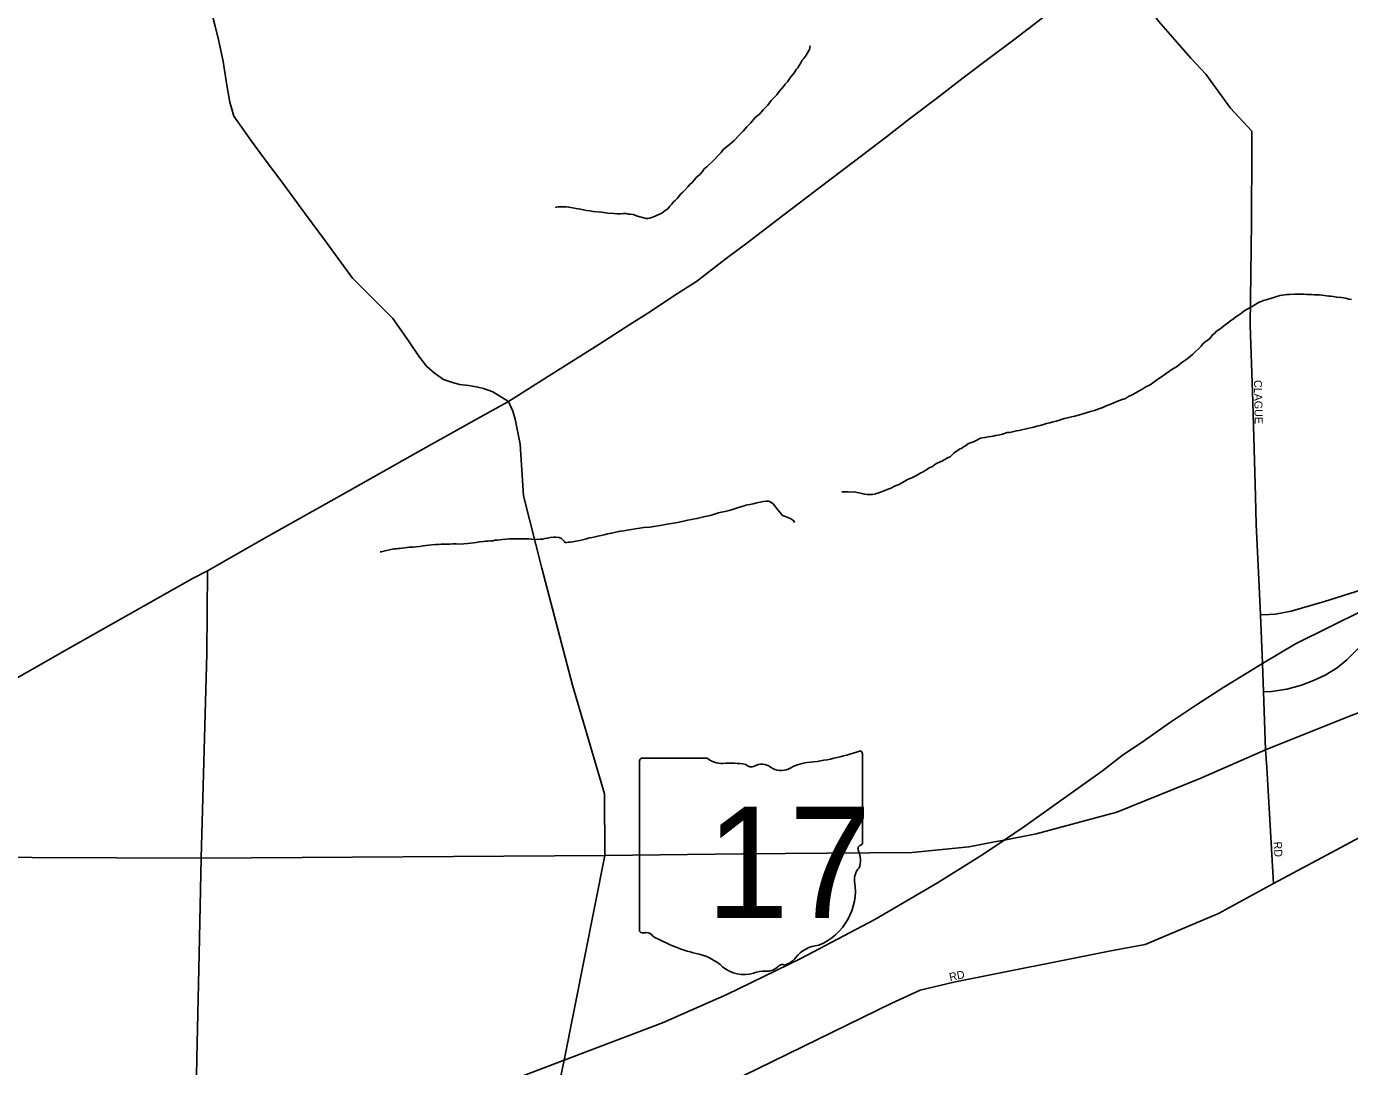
# Model space of a CAD drawing. Extents: x 2010165 to 2382125, y 1060529 to 1407316.
# Drawn here: x 2131582 to 2139850, y 1244739 to 1251239 of the extents above; entities that cross this region are included whole.
import ezdxf

# ---------------------------------------------------------------- set-up
doc = ezdxf.new("R2010")
doc.units = 0
for name, color, linetype in [('GM_X_City_Street', 7, 'Continuous'), ('GM_X_City_Street_Text', 7, 'Continuous'), ('GM_X_Interchange_Ramps', 7, 'Continuous'), ('GM_X_Interstate_Route', 7, 'Continuous'), ('GM_X_Minor_River', 7, 'Continuous'), ('GM_X_State_Location', 7, 'Continuous'), ('GM_X_State_Route', 7, 'Continuous'), ('GM_X_State_Shield', 7, 'Continuous')]:
    doc.layers.add(name, color=color, linetype=linetype)

msp = doc.modelspace()

# ---------------------------------------------------------------- linework, layer by layer
at = {"layer": 'GM_X_City_Street'}
for points in [[(2139262.6, 1248302.6), (2139246.4, 1248893.7), (2139229.9, 1249372.7), (2139237.4, 1250014), (2139239, 1250479), (2139238.9, 1250585.2), (2139106.7, 1250729.4), (2138951.7, 1250940.5), (2138858.6, 1251041.4), (2138757.8, 1251154.9), (2138656.8, 1251271.6), (2138619, 1251323.6), (2138585.9, 1251381.9), (2138552.8, 1251463.9), (2138515, 1251563.2), (2138464.5, 1251694.1)], [(2134760.7, 1243924.6), (2134781.7, 1244020.8), (2134942.2, 1244778), (2135196.8, 1246058.4), (2135194.1, 1246443), (2134994, 1247121.8), (2134802.7, 1247853), (2134689, 1248305), (2134667.5, 1248628.6), (2134636, 1248784.6), (2134621, 1248834.3), (2134594.3, 1248895)], [(2139281.1, 1247826.9), (2139267.4, 1248126.5), (2139262.6, 1248302.6)], [(2139827.5, 1246124.8), (2140192.6, 1246321), (2140591.7, 1246539.9), (2141329.2, 1246959.1), (2141729.9, 1247168.9), (2142065.6, 1247369.7), (2142493.7, 1247732.8), (2142781, 1248000.2), (2142837.3, 1248046.1)], [(2139325.8, 1246718.6), (2139313.3, 1247081), (2139307.3, 1247257.6), (2139293.3, 1247562.6), (2139281.1, 1247826.9)], [(2139332.5, 1246607.1), (2139325.8, 1246718.6)], [(2139376, 1245882.3), (2139332.5, 1246607.1)], [(2134760.7, 1243924.6), (2135320.2, 1244318.5), (2136990.7, 1245134.9), (2137167.3, 1245216), (2137377.1, 1245265), (2138357.9, 1245460.7), (2138572.2, 1245501.1), (2139030.3, 1245694.4), (2139376, 1245882.3), (2139827.5, 1246124.8)]]:
    msp.add_lwpolyline(points, dxfattribs=at)
at = {"layer": 'GM_X_Interchange_Ramps'}
for points in [[(2140506.4, 1247821.2), (2140483.6, 1247888.8), (2140122.8, 1247780.5), (2139693.1, 1247645.4), (2139485, 1247584.7), (2139387.6, 1247566.4), (2139347, 1247563.9), (2139293.3, 1247562.6)], [(2139313.3, 1247081), (2139362.5, 1247081.8), (2139457.8, 1247097.3), (2139550.6, 1247123), (2139625.3, 1247151.4), (2139697.5, 1247184.9), (2139772.3, 1247231.3), (2139834.1, 1247280.3), (2140030, 1247473.7), (2140086.7, 1247527.9), (2140148.5, 1247579.4), (2140225.9, 1247623.3), (2140640.8, 1247801.1), (2140620.2, 1247862.1)]]:
    msp.add_lwpolyline(points, dxfattribs=at)
at = {"layer": 'GM_X_Interstate_Route'}
msp.add_lwpolyline([(2132608.6, 1243891.8), (2132749.3, 1243945.3), (2133502.4, 1244231.2), (2134099, 1244457.8), (2134942.2, 1244778), (2135556.5, 1245011.9), (2135958, 1245187.9), (2136421.9, 1245412.8), (2136884.2, 1245658.5), (2137275.4, 1245886.2), (2137558.2, 1246064.7), (2137691, 1246154.1), (2137820.9, 1246241.6), (2138306.6, 1246587.6), (2138428.8, 1246681.8), (2138569, 1246776), (2138725.3, 1246886.2), (2138893.6, 1246998.4), (2139063.9, 1247110.6), (2139307.3, 1247257.6), (2139512.6, 1247380.2), (2139933.1, 1247588.5), (2140013.9, 1247623.4)], dxfattribs=at)
at = {"layer": 'GM_X_Minor_River'}
for points in [[(2136479.5, 1251118.2), (2136475.5, 1251096.1), (2136453.6, 1251059.9), (2136439.6, 1251039.8), (2136429.6, 1251027.7), (2136421.6, 1251011.6), (2136411.7, 1250995.6), (2136401.7, 1250981.5), (2136391.7, 1250969.4), (2136383.7, 1250955.3), (2136373.7, 1250941.3), (2136359.7, 1250925.2), (2136349.8, 1250911.1), (2136337.8, 1250893), (2136323.8, 1250878.9), (2136313.8, 1250864.8), (2136299.8, 1250848.7), (2136285.8, 1250832.6), (2136271.8, 1250812.5), (2136253.8, 1250794.4), (2136235.9, 1250776.2), (2136215.9, 1250748.1), (2136187.9, 1250719.9), (2136161.9, 1250691.7), (2136135.9, 1250669.6), (2136107.9, 1250637.4), (2136083.9, 1250611.2), (2136059.9, 1250585.1), (2136034, 1250556.9), (2136004, 1250526.7), (2135976, 1250502.5), (2135951.9, 1250482.4), (2135935.9, 1250470.3), (2135924, 1250452.2), (2135902, 1250430), (2135882, 1250407.9), (2135834, 1250361.6), (2135818, 1250349.5), (2135806, 1250333.4), (2135792, 1250315.3), (2135776, 1250301.2), (2135764, 1250293.1), (2135756, 1250281.1), (2135742, 1250265), (2135728, 1250250.9), (2135714, 1250236.8), (2135698, 1250218.6), (2135684, 1250204.6), (2135670, 1250190.5), (2135658, 1250176.4), (2135648.1, 1250164.3), (2135636.1, 1250152.2), (2135626.1, 1250144.2), (2135612.1, 1250126.1), (2135602.1, 1250116), (2135590.1, 1250099.9), (2135574.1, 1250089.8), (2135552.1, 1250071.7), (2135534, 1250063.6), (2135520, 1250057.5), (2135510, 1250053.5), (2135489.9, 1250045.4), (2135475.9, 1250041.3), (2135465.9, 1250039.3), (2135453.8, 1250039.3)], [(2135453.8, 1250039.3), (2135399.6, 1250053.1), (2135373.5, 1250063.1), (2135355.4, 1250065.1), (2135343.4, 1250067), (2135329.3, 1250071), (2135313.3, 1250070.9), (2135295.2, 1250068.9), (2135273.1, 1250068.8), (2135253.1, 1250070.8), (2135214.9, 1250072.6), (2135202.9, 1250074.6), (2135190.8, 1250076.6), (2135174.8, 1250078.5), (2135122.6, 1250082.4), (2135102.5, 1250086.3), (2135082.4, 1250088.3), (2135064.4, 1250092.2), (2135042.3, 1250098.2), (2135018.2, 1250102.1), (2134994.1, 1250106.1), (2134972, 1250110), (2134953.9, 1250111.9), (2134937.9, 1250111.9), (2134925.8, 1250111.9), (2134913.8, 1250111.8), (2134903.8, 1250111.8), (2134889.7, 1250109.8), (2134891.7, 1250109.7), (2134889.7, 1250109.8)], [(2139862.3, 1249533.4), (2139846.2, 1249535.4), (2139826.1, 1249541.3), (2139800, 1249545.3), (2139769.9, 1249547.2), (2139747.8, 1249551.1), (2139733.8, 1249553.1), (2139719.8, 1249553.1), (2139705.7, 1249555), (2139693.6, 1249557), (2139677.6, 1249558.9), (2139661.5, 1249560.9), (2139645.5, 1249562.8), (2139629.4, 1249562.8), (2139615.4, 1249564.8), (2139599.3, 1249564.7), (2139583.3, 1249564.7), (2139563.2, 1249566.6), (2139545.1, 1249566.6), (2139527.1, 1249566.5), (2139507, 1249566.4), (2139474.9, 1249564.3), (2139458.8, 1249564.3), (2139444.8, 1249562.2), (2139428.8, 1249560.1), (2139414.7, 1249558.1), (2139404.7, 1249554.1), (2139394.7, 1249552), (2139382.6, 1249548), (2139370.6, 1249543.9), (2139356.6, 1249539.9), (2139342.6, 1249535.8), (2139328.5, 1249529.7), (2139312.5, 1249525.7), (2139298.5, 1249519.6), (2139286.4, 1249515.6), (2139274.4, 1249509.5), (2139258.4, 1249499.4), (2139238.4, 1249487.3), (2139214.3, 1249475.2), (2139192.3, 1249461.1), (2139174.3, 1249447), (2139156.3, 1249434.9), (2139140.3, 1249424.8), (2139122.3, 1249410.7), (2139108.3, 1249400.6), (2139096.2, 1249390.5), (2139062.2, 1249366.3), (2139050.2, 1249356.3), (2139040.2, 1249348.2), (2139028.2, 1249340.1), (2139018.2, 1249334.1), (2139004.2, 1249318), (2138994.2, 1249311.9), (2138986.2, 1249299.9), (2138974.2, 1249287.8), (2138960.2, 1249275.7), (2138946.2, 1249265.6), (2138934.2, 1249255.6), (2138922.2, 1249241.5), (2138906.2, 1249225.4), (2138888.2, 1249207.3), (2138870.2, 1249191.1), (2138854.2, 1249177.1), (2138826.2, 1249154.9), (2138808.2, 1249142.8), (2138792.1, 1249130.7), (2138774.1, 1249116.6), (2138754.1, 1249104.5), (2138736.1, 1249092.4), (2138718.1, 1249080.3), (2138698.1, 1249066.2), (2138676, 1249050.1), (2138652, 1249033.9), (2138628, 1249015.8), (2138604, 1248999.7), (2138577.9, 1248987.5), (2138557.9, 1248975.4), (2138535.9, 1248961.3), (2138513.9, 1248949.2), (2138491.8, 1248937.1), (2138469.8, 1248927), (2138449.8, 1248914.9), (2138429.7, 1248906.8), (2138411.7, 1248900.7), (2138395.7, 1248894.6), (2138377.6, 1248886.6), (2138351.6, 1248876.4), (2138329.5, 1248868.3), (2138307.5, 1248858.2), (2138283.4, 1248850.1), (2138255.4, 1248840), (2138231.3, 1248831.9)], [(2138231.3, 1248831.9), (2138211.3, 1248825.8), (2138191.2, 1248819.7), (2138177.2, 1248815.7), (2138133.1, 1248803.5), (2138113, 1248799.4), (2138095, 1248795.4), (2138079, 1248791.3), (2138066.9, 1248789.2), (2138054.9, 1248785.2), (2138036.9, 1248779.1), (2138016.8, 1248773), (2137998.8, 1248769), (2137976.7, 1248762.9), (2137956.7, 1248756.8), (2137938.6, 1248750.7), (2137916.6, 1248744.6), (2137896.5, 1248740.6), (2137876.5, 1248734.5), (2137856.4, 1248730.4), (2137838.4, 1248726.3), (2137820.3, 1248722.2), (2137802.3, 1248718.2), (2137786.3, 1248714.1), (2137768.2, 1248712.1), (2137752.2, 1248708), (2137736.1, 1248703.9), (2137722.1, 1248701.9), (2137710.1, 1248701.8), (2137682, 1248691.7), (2137655.9, 1248685.6), (2137637.9, 1248683.6), (2137623.8, 1248679.5), (2137609.8, 1248677.4), (2137591.8, 1248673.4), (2137571.7, 1248669.3), (2137555.6, 1248667.2), (2137543.6, 1248665.2), (2137521.6, 1248653.1), (2137499.6, 1248643), (2137481.5, 1248636.9), (2137469.5, 1248632.8), (2137449.5, 1248618.7), (2137437.4, 1248612.7), (2137427.4, 1248604.6), (2137413.4, 1248596.5), (2137403.4, 1248590.5), (2137393.4, 1248584.4), (2137379.4, 1248574.4), (2137363.4, 1248558.3), (2137353.4, 1248550.2), (2137341.4, 1248546.1), (2137321.3, 1248532), (2137303.3, 1248521.9), (2137287.3, 1248515.9), (2137273.3, 1248509.8), (2137259.2, 1248501.7), (2137243.2, 1248489.6), (2137223.2, 1248479.6), (2137207.2, 1248467.5), (2137191.2, 1248459.4), (2137181.2, 1248453.3), (2137171.1, 1248449.3), (2137161.1, 1248443.2), (2137151.1, 1248437.2), (2137131.1, 1248427.1), (2137115.1, 1248419), (2137099, 1248412.9), (2137087, 1248406.9), (2137071, 1248396.8), (2137053, 1248386.7), (2137034.9, 1248376.6), (2137016.9, 1248370.5), (2137002.9, 1248364.5), (2136988.9, 1248356.4), (2136950.8, 1248340.2), (2136934.7, 1248334.1), (2136918.7, 1248328.1), (2136902.7, 1248322), (2136888.6, 1248317.9), (2136878.6, 1248315.9), (2136868.6, 1248313.9), (2136856.6, 1248313.8), (2136834.5, 1248313.8), (2136820.4, 1248315.7), (2136810.4, 1248317.7), (2136794.3, 1248321.7), (2136774.2, 1248325.6), (2136756.2, 1248329.6), (2136744.1, 1248329.5), (2136716, 1248331.5), (2136704, 1248331.4), (2136689.9, 1248331.4), (2136683.9, 1248331.3), (2136677.9, 1248331.3)], [(2136381.6, 1248139.8), (2136377.5, 1248149.8), (2136359.4, 1248161.8), (2136339.3, 1248169.7), (2136325.3, 1248175.7), (2136307.2, 1248183.7), (2136289.1, 1248203.7), (2136277, 1248217.7), (2136266.9, 1248229.7), (2136258.8, 1248243.7), (2136246.7, 1248257.7), (2136228.6, 1248267.7), (2136218.6, 1248271.7), (2136204.5, 1248271.6), (2136188.5, 1248269.6), (2136166.4, 1248265.5), (2136146.4, 1248261.4), (2136124.3, 1248255.3), (2136102.3, 1248251.2), (2136088.2, 1248249.2), (2136078.2, 1248247.2), (2136066.2, 1248243.1), (2136052.1, 1248239.1), (2136032.1, 1248233), (2136000, 1248222.8), (2135974, 1248214.7), (2135947.9, 1248208.6), (2135923.8, 1248202.5), (2135905.8, 1248198.5), (2135881.8, 1248190.3), (2135853.7, 1248182.2), (2135823.6, 1248176.1), (2135795.5, 1248170), (2135771.5, 1248163.9), (2135747.4, 1248159.8), (2135705.3, 1248151.7), (2135679.2, 1248145.6), (2135651.2, 1248139.4), (2135625.1, 1248135.4), (2135599, 1248131.3), (2135574.9, 1248127.2), (2135552.9, 1248123.1), (2135528.8, 1248119), (2135502.7, 1248114.9), (2135476.7, 1248110.8), (2135440.6, 1248106.7), (2135414.5, 1248102.6), (2135386.4, 1248098.5), (2135362.4, 1248094.4), (2135336.3, 1248090.3), (2135314.2, 1248086.2), (2135292.2, 1248084.1), (2135264.1, 1248078), (2135238, 1248071.9), (2135213.9, 1248067.8), (2135191.9, 1248061.8), (2135173.9, 1248057.7), (2135151.8, 1248053.6), (2135135.7, 1248049.5), (2135117.7, 1248045.5), (2135101.7, 1248043.4), (2135091.6, 1248041.4), (2135081.6, 1248037.3), (2135039.5, 1248027.1), (2135015.4, 1248023.1), (2134993.4, 1248019), (2134979.3, 1248016.9), (2134969.3, 1248016.9), (2134951.3, 1248012.8), (2134943.2, 1248022.8), (2134925.1, 1248038.8), (2134911, 1248044.8), (2134890.9, 1248046.8), (2134876.9, 1248046.7), (2134854.8, 1248044.6), (2134838.8, 1248040.6), (2134820.7, 1248038.5), (2134806.7, 1248034.4), (2134792.7, 1248034.4), (2134778.6, 1248032.3), (2134738.5, 1248034.2), (2134720.4, 1248036.2), (2134700.4, 1248036.1), (2134680.3, 1248036.1), (2134666.2, 1248036), (2134652.2, 1248036), (2134636.1, 1248035.9), (2134616.1, 1248037.9), (2134600, 1248037.8), (2134579.9, 1248035.7), (2134555.9, 1248033.6), (2134539.8, 1248031.6), (2134525.8, 1248029.5), (2134509.7, 1248027.5), (2134497.7, 1248025.4), (2134483.7, 1248025.4), (2134467.6, 1248023.3), (2134453.6, 1248021.3), (2134437.5, 1248019.2), (2134413.5, 1248017.1), (2134391.4, 1248013.1)], [(2134391.4, 1248013.1), (2134359.3, 1248008.9), (2134337.2, 1248006.9), (2134315.2, 1248004.8), (2134291.1, 1248002.7), (2134267, 1248004.6), (2134246.9, 1248004.6), (2134226.9, 1248004.5), (2134208.8, 1248004.5), (2134190.8, 1248004.4), (2134172.7, 1248004.3), (2134158.7, 1248002.3), (2134138.6, 1248002.2), (2134114.5, 1248000.1), (2134096.5, 1247998.1), (2134078.4, 1247996), (2134060.4, 1247994), (2134038.3, 1247989.9), (2134016.2, 1247987.8), (2133998.2, 1247985.7), (2133982.1, 1247985.7), (2133972.1, 1247985.6), (2133960.1, 1247983.6), (2133946, 1247981.6), (2133928, 1247979.5), (2133915.9, 1247977.4), (2133903.9, 1247977.4), (2133893.9, 1247975.4), (2133881.8, 1247975.3), (2133867.8, 1247971.3), (2133815.7, 1247959.1), (2133799.6, 1247955), (2133791.6, 1247955)]]:
    msp.add_lwpolyline(points, dxfattribs=at)
at = {"layer": 'GM_X_State_Route'}
for points in [[(2134037.5, 1249173.1), (2133969.2, 1249273.4), (2133871.4, 1249413.7), (2133619.5, 1249666.1), (2133457.2, 1249888.6), (2133319, 1250075.1), (2133170.8, 1250277.6), (2133086.7, 1250389.9), (2132988.5, 1250522.2), (2132902.4, 1250642.5), (2132878.4, 1250678.6), (2132852.3, 1250766.8), (2132834.3, 1250873.1), (2132810.3, 1251019.4), (2132784.3, 1251147.8), (2132762.2, 1251242), (2132732.2, 1251354.3), (2132696.2, 1251492.6), (2132648.1, 1251647), (2132604, 1251779.3), (2132541.9, 1251969.7), (2132473.9, 1252154.2), (2132405.7, 1252318.6), (2132398.2, 1252336.4)], [(2134594.3, 1248895), (2134805.5, 1249028.2), (2135157.8, 1249250.5), (2135352.5, 1249377.4), (2135482.6, 1249458.6), (2135621.3, 1249550.8), (2135713.5, 1249609.9), (2135768.7, 1249646.2), (2135844.4, 1249702.9), (2135954, 1249788.1), (2136083.2, 1249884.2), (2136306.3, 1250056.1), (2136542.8, 1250235.8), (2136747.7, 1250390.3), (2136955.8, 1250550.3), (2137099.3, 1250661.5), (2137268, 1250790), (2137435.8, 1250918.4), (2137595.9, 1251039.8), (2137752.7, 1251156.5), (2137930.9, 1251293.6)], [(2134594.3, 1248895), (2134495.7, 1248954.9), (2134438.9, 1248977), (2134402.7, 1248985.7), (2134345.9, 1248994.3), (2134288.4, 1249000.6), (2134237.2, 1249016.4), (2134189.1, 1249033.7), (2134131.5, 1249071.6), (2134082.7, 1249115.7), (2134040.1, 1249169.3), (2134037.5, 1249173.1)], [(2132714.3, 1247837.2), (2133091.8, 1248053.1), (2133590, 1248333), (2134058.2, 1248597), (2134398.7, 1248787), (2134594.3, 1248895)], [(2128973.3, 1246056.5), (2129572.3, 1246296.2), (2130329, 1246586.2), (2130569.1, 1246686.6), (2130779.9, 1246781.7), (2130980.1, 1246871.6), (2131125.2, 1246944.1), (2131303.3, 1247043.4), (2131867.7, 1247363.5), (2132623.6, 1247790.7), (2132714.3, 1247837.2)], [(2132674.5, 1246041.8), (2132708.9, 1247320.3), (2132714.3, 1247837.2)], [(2139474.8, 1246778.1), (2139877.2, 1246938.7), (2139922, 1246956.2)], [(2137632.1, 1246142.6), (2137691, 1246154.1), (2137892.5, 1246193.6), (2138396.1, 1246329.4), (2138921.1, 1246541.8), (2139325.8, 1246718.6), (2139474.8, 1246778.1)], [(2132674.5, 1246041.8), (2132674.5, 1246041.8), (2135196.8, 1246058.4), (2136059.2, 1246067.7), (2137117.7, 1246076.4), (2137471.6, 1246111.2), (2137632.1, 1246142.6)], [(2128973.3, 1246056.5), (2132674.5, 1246041.8)], [(2132661.5, 1245442.9), (2132674.5, 1246041.8)], [(2132647.3, 1244789.6), (2132661.5, 1245442.9)], [(2132608.5, 1243730.8), (2132608.6, 1243891.8), (2132611.7, 1243960.7), (2132617.9, 1244093.9), (2132631.2, 1244383.2), (2132632.5, 1244410.7), (2132644.9, 1244680.7), (2132647.3, 1244789.6)]]:
    msp.add_lwpolyline(points, dxfattribs=at)
at = {"layer": 'GM_X_State_Shield'}
for p, q in [((2136805.9, 1246140), (2136805.9, 1246692.7)), ((2135413.7, 1246648.4), (2135413.7, 1245591.7)), ((2135835.1, 1246666.5), (2135427.4, 1246666.5)), ((2136805.8, 1246140.1), (2136805.9, 1246140))]:
    msp.add_line(p, q, dxfattribs=at)
for centre, radius, start, end in [((2136310, 1248107.1), 1476.4, 275.84447, 288.90645), ((2136790.5, 1246695), 15.5, 351.86209, 97.738), ((2135429.7, 1246650.6), 16.1, 98.1301, 188.1301), ((2135932.2, 1246789.2), 156.4, 231.61951, 271.11188), ((2135984.1, 1246073.3), 561.6, 80.48669, 94.98827), ((2136111.6, 1246656.1), 45.1, 219.79206, 297.10237), ((2136177.8, 1246534), 93.8, 54.46668, 119.14113), ((2136299, 1246701.5), 112.9, 233.85621, 294.82819), ((2136498.3, 1246343.8), 297, 97.34618, 120.76885), ((2136802.3, 1246099.4), 24, 107.94398, 210.33697), ((2136789.4, 1246137.9), 16.6, 289.60381, 7.73413), ((2136649.7, 1246029.5), 144, 340.03296, 23.64957), ((2136861.4, 1245908.7), 104.8, 136.8065, 186.92959), ((2136392.7, 1245838.4), 369.3, 292.30889, 8.98584), ((2135429.8, 1245589.4), 16.3, 171.95839, 258.30661), ((2135432.3, 1245697.5), 124.2, 267.33899, 280.60386), ((2135457.7, 1245530.8), 44.8, 29.74838, 93.27175), ((2136023, 1246480.1), 1066.1, 240.41292, 257.1985), ((2136548.4, 1245295.1), 202.2, 94.40312, 142.57675), ((2135705.1, 1245117), 333.6, 47.18416, 75.83597), ((2136203.7, 1245446.4), 112.8, 268.77702, 315.54927), ((2136305.7, 1245344.1), 31.8, 65.75173, 132.64842), ((2136292.2, 1245489.3), 119.3, 282.87319, 323.27711), ((2136065.9, 1245525.5), 211.7, 230.70037, 286.29184), ((2136188.2, 1245160.2), 173.9, 85.69512, 111.20995)]:
    msp.add_arc(centre, radius, start, end, dxfattribs=at)

# ---------------------------------------------------------------- texts
at = {"layer": 'GM_X_City_Street_Text'}
for s, rotation, p in [('CLAGUE', 271.02248, (2139252.9, 1249029.3)), ('RD', 273.01099, (2139376.1, 1246143.2)), ('RD', 11.87935, (2137354.2, 1245272))]:
    msp.add_text(s, height=50, rotation=rotation, dxfattribs=at).set_placement(p)
at = {"layer": 'GM_X_State_Location'}
for s in ['s', 'r']:
    msp.add_text(s, height=1, dxfattribs=at).set_placement((2136094.1, 1246049.8))
msp.add_text('17', height=1, rotation=0.00001, dxfattribs=at).set_placement((2135842.3, 1245977))
at = {"layer": 'GM_X_State_Shield'}
msp.add_text('17', height=696.1, dxfattribs=at).set_placement((2135828.2, 1245666.2))

doc.saveas('drawing.dxf')
